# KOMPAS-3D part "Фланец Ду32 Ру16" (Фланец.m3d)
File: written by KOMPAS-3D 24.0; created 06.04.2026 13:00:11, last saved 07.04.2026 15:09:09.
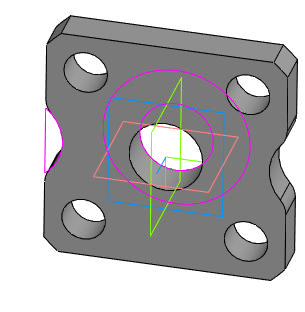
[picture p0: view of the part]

Document properties: Автор: R2D2; Полное имя файла: E:\Работа\Зайцев\Солянка\VSR1-13V-PED-F Клапан запорно-регулирующий DN.ru\DN32\исходные материалы\Фланец.m3d

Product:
- Component [standard]: (unnamed)  | qty 1  | Материал: ВЧ40 ГОСТ 7293-85 (density 7200 kg/m3); Масса: 1.58; additional columns: 32-16-01-1-B-ВЧ40-II-dв 39; Фланец квадратный; ГОСТ 33259-2015
- Part/product: Фланец Ду32 Ру16
    Масса: 1.157211

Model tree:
1. Эскиз:1
2. Элемент выдавливания:1
3. Скругление:1  (with: Ребро.Элемент выдавливания:1)
     Радиус = 10
4. Зеркальный массив:1
5. Экземпляр ( 1 )
6. Экземпляр ( 2 )  (with: Элемент выдавливания:1, Скругление:1)
7. Эскиз:2
8. Элемент выдавливания:2
     Расстояние 1 = -18
9. Эскиз:3  (with: Грань.Элемент выдавливания:2, Ребро.Элемент выдавливания:2)
10. Элемент выдавливания:3  (with: Грань.Элемент выдавливания:2)
     Расстояние 2 = 16
11. Эскиз:4  (with: Грань.Элемент выдавливания:2, Ребро.Элемент выдавливания:2)
12. Элемент выдавливания:4
13. Массив по концентрической сетке:1  (with: Элемент выдавливания:4, Эскиз:4)  (4 pattern instances)
     Шаг 2 = 360

Expressions: v108*2
Referenced files in C:\Program Files\ASCON\KOMPAS-3D v24\Libs\PolynomLib\DATA\vault\Methods\Kompas\3D\: PLib_Flange_GOST_33259_1401.m3d
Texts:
  BOSimple***Material:38d6725a-5efe-48e1-b177-a7817acb862a
  BOSimple***PART:50a46c37-6122-73fa-e80a-0871b01edfc1***SHORTLOC:B6A6_23E38AE8DB154823[II;1;Квадратный;32;16;39;0;ВЧ40 ГОСТ 7293-85]
  Ch34
  Плоскость XY.Начало координат
  Ось Z.Начало координат
  Плоскость ZY.Начало координат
